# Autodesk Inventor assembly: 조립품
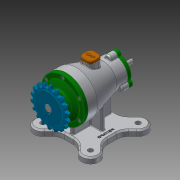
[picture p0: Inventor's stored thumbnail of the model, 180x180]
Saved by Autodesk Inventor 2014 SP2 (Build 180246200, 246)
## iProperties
Created: 2018-03
Part Number: 조립품
Document SubType Name: Assembly
Designer: 거성
Author: 거성
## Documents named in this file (15)
- C:\Users\거성\Desktop\480308V1011\조립품.iam
- C:\Users\거성\Desktop\480308V1011\본체.ipt
- C:\Users\거성\Desktop\480308V1011\앞커버.ipt
- C:\Users\거성\Desktop\480308V1011\뒤커버.ipt
- C:\Users\거성\Desktop\480308V1011\오일 실 17 30 8.ipt
- C:\Users\거성\Desktop\480308V1011\오일 실 10 20 7.ipt
- C:\Users\거성\Desktop\480308V1011\베어링-6203.ipt
- C:\Users\거성\Desktop\480308V1011\베어링-6200.ipt
- C:\Users\거성\Desktop\480308V1011\축.ipt
- C:\Users\거성\Desktop\480308V1011\키 5 x 5.ipt
- 키 5 x 5.ipt
- C:\Users\거성\Desktop\480308V1011\스프로킷.ipt
- C:\Users\거성\Desktop\480308V1011\볼트 M4 x 12.ipt
- 볼트 M4 x 12.ipt
- C:\Users\거성\Desktop\480308V1011\마개.ipt
